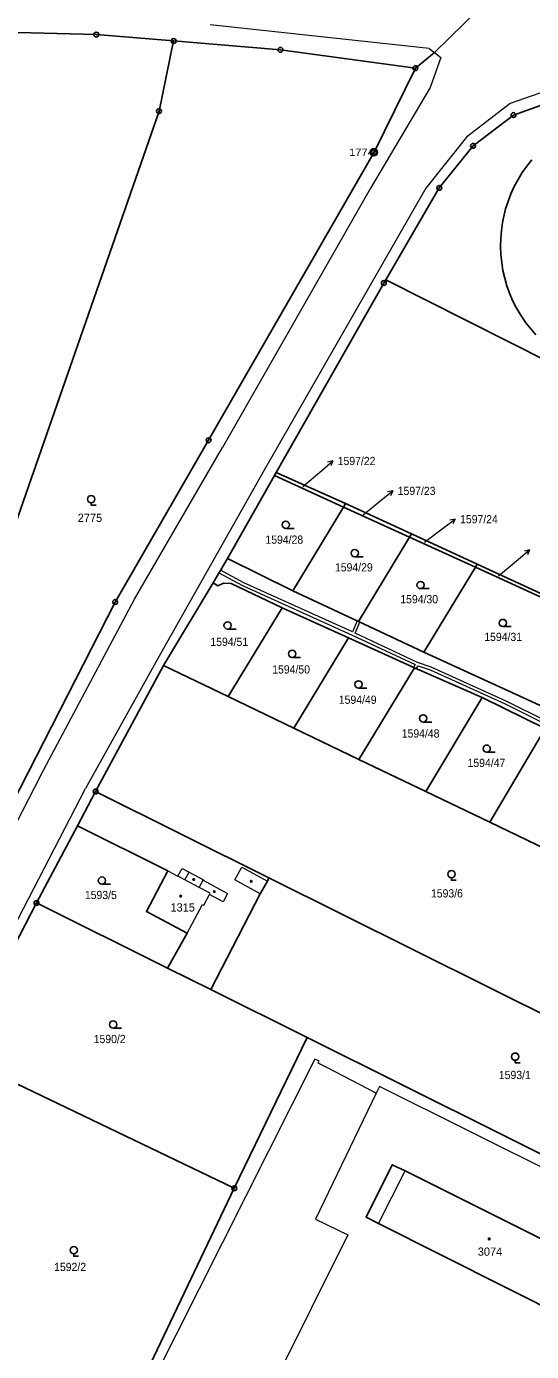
# Model space of a CAD drawing. Extents: x -679733 to -673243, y -1075091 to -1066557.
# Drawn here: x -677661.5 to -677557.1, y -1071678.8 to -1071405 of the extents above; entities that cross this region are included whole.
import ezdxf
from ezdxf.enums import TextEntityAlignment as Align

# ---------------------------------------------------------------- set-up
doc = ezdxf.new("R2010")
doc.units = 0
doc.header["$LTSCALE"] = 0.68
for name, color, linetype, lineweight in [('1', 7, 'Continuous', 25), ('13', 7, 'Continuous', 13), ('3', 7, 'Continuous', 25), ('4', 7, 'Continuous', 13), ('5', 7, 'Continuous', 25), ('7', 7, 'Continuous', 13), ('8', 7, 'Continuous', 25)]:
    doc.layers.add(name, color=color, linetype=linetype, lineweight=lineweight)
doc.layers.add('2', color=7, linetype='Continuous')

msp = doc.modelspace()

# ---------------------------------------------------------------- linework, layer by layer
at = {"layer": '1'}
for p, q in [((-677609.85, -1071497.19), (-677595.5, -1071503.6)), ((-677595.93, -1071504.31), (-677595.5, -1071503.6)), ((-677582.29, -1071510.53), (-677581.89, -1071509.87)), ((-677568.67, -1071516.74), (-677568.3, -1071516.13)), ((-677608.6, -1071525.12), (-677619.78, -1071543.45)), ((-677594.92, -1071531.34), (-677606.2, -1071549.97)), ((-677619.78, -1071543.45), (-677633.15, -1071537.04)), ((-677581.28, -1071537.54), (-677592.73, -1071556.43)), ((-677567.25, -1071543.65), (-677578.91, -1071563.07)), ((-677554.21, -1071550.04), (-677565.65, -1071569.43)), ((-677475.97, -1071648.33), (-677611.33, -1071580.93)), ((-677632.29, -1071599.54), (-677659.4, -1071586.1)), ((-677603.41, -1071613.91), (-677623.32, -1071603.99))]:
    msp.add_line(p, q, dxfattribs=at)
for points in [[(-677581.06, -1071413.63), (-677577.13, -1071410.43), (-677571, -1071404.43), (-677567.33, -1071400.82)], [(-677668.67, -1071406.15), (-677647.03, -1071406.71), (-677631.04, -1071408.03)], [(-677631.04, -1071408.03), (-677634.06, -1071422.51), (-677671.93, -1071531.12), (-677696.09, -1071583.01)], [(-677631.04, -1071408.03), (-677608.96, -1071409.86), (-677581.06, -1071413.63)], [(-677581.06, -1071413.63), (-677589.62, -1071430.98), (-677623.81, -1071490.51), (-677643.12, -1071523.94), (-677667.72, -1071571.95), (-677679.36, -1071592.98)], [(-677524.38, -1071416.45), (-677547.16, -1071418.48), (-677560.78, -1071423.33), (-677569.14, -1071429.68), (-677576.12, -1071438.38), (-677587.19, -1071457.4)], [(-677556.129, -1071468.742), (-677557.215, -1071467.524), (-677558.225, -1071466.241), (-677558.508, -1071465.851), (-677559.412, -1071464.492), (-677560.232, -1071463.081), (-677560.964, -1071461.622), (-677561.605, -1071460.121), (-677562.153, -1071458.583), (-677562.606, -1071457.015), (-677562.962, -1071455.422), (-677563.22, -1071453.81), (-677563.385, -1071452.16), (-677563.451, -1071450.503), (-677563.416, -1071448.846), (-677563.282, -1071447.193), (-677563.048, -1071445.552), (-677562.716, -1071443.927), (-677562.406, -1071442.734), (-677561.905, -1071441.154), (-677561.31, -1071439.606), (-677560.622, -1071438.097), (-677559.845, -1071436.633), (-677558.981, -1071435.218), (-677558.033, -1071433.857), (-677557.005, -1071432.556)], [(-677609.85, -1071497.19), (-677587.59, -1071458.03), (-677587.19, -1071457.4)], [(-677587.19, -1071457.4), (-677502.54, -1071500), (-677433.93, -1071533.74), (-677395.28, -1071552.08)], [(-677675.7, -1071617.62), (-677659.4, -1071586.1), (-677650.93, -1071570.15), (-677647.17, -1071563.08), (-677633.15, -1071537.04), (-677622.89, -1071519.94), (-677619.94, -1071514.94), (-677610.19, -1071497.8), (-677609.85, -1071497.19)], [(-677606.39, -1071521.59), (-677595.93, -1071504.31), (-677610.19, -1071497.8)], [(-677592.82, -1071527.94), (-677582.29, -1071510.53), (-677595.93, -1071504.31)], [(-677595.5, -1071503.6), (-677581.89, -1071509.87), (-677568.3, -1071516.13), (-677541.06, -1071528.61), (-677527.52, -1071534.91), (-677500.29, -1071547.58), (-677486.66, -1071553.87), (-677473.03, -1071560.16), (-677459.29, -1071566.4)], [(-677579.33, -1071534.29), (-677568.67, -1071516.74), (-677582.29, -1071510.53)], [(-677511.44, -1071565.66), (-677538.35, -1071553.02), (-677552.08, -1071546.78), (-677579.33, -1071534.29), (-677592.82, -1071527.94), (-677606.39, -1071521.59), (-677619.94, -1071514.94)], [(-677552.08, -1071546.78), (-677541.41, -1071529.19), (-677568.67, -1071516.74)], [(-677622.89, -1071519.94), (-677621.89, -1071520.58), (-677620.73, -1071520.03), (-677619.17, -1071520.07), (-677608.6, -1071525.12), (-677594.92, -1071531.34), (-677581.28, -1071537.54), (-677567.25, -1071543.65), (-677554.21, -1071550.04), (-677540.61, -1071556.25), (-677526.95, -1071562.58), (-677513.43, -1071569.04), (-677499.77, -1071575.57), (-677486.12, -1071581.93)], [(-677475.97, -1071648.33), (-677460.19, -1071618.11), (-677484.77, -1071607.17), (-677497.84, -1071601.35), (-677511.65, -1071595.21), (-677525.11, -1071588.88), (-677538.62, -1071582.4), (-677552.22, -1071575.88), (-677565.65, -1071569.43), (-677578.91, -1071563.07), (-677592.73, -1071556.43), (-677606.2, -1071549.97), (-677619.78, -1071543.45)], [(-677623.32, -1071603.99), (-677613.14, -1071584.19), (-677611.67, -1071581.57), (-677611.33, -1071580.93), (-677647.17, -1071563.08)], [(-677650.93, -1071570.15), (-677632.21, -1071579.49), (-677636.67, -1071587.87), (-677628.27, -1071592.32), (-677632.29, -1071599.54), (-677623.32, -1071603.99)], [(-677495.95, -1071734.2), (-677491.54, -1071711.22), (-677490.81, -1071708.2), (-677482.55, -1071674.1), (-677603.41, -1071613.91), (-677618.5, -1071645.05), (-677641.36, -1071692.91)], [(-677618.5, -1071645.05), (-677675.7, -1071617.62), (-677700.06, -1071664.74)]]:
    msp.add_lwpolyline(points, dxfattribs=at)
msp.add_lwpolyline([(-677536.2, -1071678.67), (-677588.68, -1071652.34), (-677591.25, -1071651), (-677585.84, -1071640.17), (-677583.21, -1071641.44), (-677530.69, -1071667.67)], close=True, dxfattribs=at)
at = {"layer": '13'}
msp.add_lwpolyline([(-677553.99, -1071548.56), (-677562.27, -1071544.42), (-677577.81, -1071537.38), (-677580.62, -1071536.42), (-677593.54, -1071530.36), (-677592.54, -1071528.07), (-677592.82, -1071527.94), (-677593.11, -1071527.8), (-677594.09, -1071530.11), (-677616.54, -1071519.99), (-677621.37, -1071517.36), (-677621.67, -1071517.88), (-677616.82, -1071520.51), (-677594.11, -1071530.76), (-677581.09, -1071536.86), (-677581.47, -1071537.45), (-677581.28, -1071537.54), (-677580.9, -1071537.7), (-677580.51, -1071537.09), (-677578.03, -1071537.94), (-677562.51, -1071544.96), (-677553.97, -1071549.25)], dxfattribs=at)
at = {"layer": '3'}
for p, q in [((-677607.863, -1071508.71), (-677606.113, -1071508.71)), ((-677593.603, -1071514.58), (-677591.853, -1071514.58)), ((-677579.993, -1071521.17), (-677578.243, -1071521.17)), ((-677619.883, -1071529.51), (-677618.133, -1071529.51)), ((-677562.983, -1071529.01), (-677561.233, -1071529.01)), ((-677606.543, -1071535.38), (-677604.793, -1071535.38)), ((-677592.823, -1071541.7), (-677591.073, -1071541.7)), ((-677579.443, -1071548.72), (-677577.693, -1071548.72)), ((-677566.323, -1071554.97), (-677564.573, -1071554.97)), ((-677645.863, -1071582.23), (-677644.113, -1071582.23)), ((-677643.543, -1071611.95), (-677641.793, -1071611.95))]:
    msp.add_line(p, q, dxfattribs=at)
for points in [[(-677648.09, -1071503.442), (-677648.09, -1071503.94), (-677647.089, -1071503.94)], [(-677573.61, -1071580.902), (-677573.61, -1071581.4), (-677572.609, -1071581.4)], [(-677560.43, -1071618.602), (-677560.43, -1071619.1), (-677559.429, -1071619.1)], [(-677651.69, -1071658.572), (-677651.69, -1071659.07), (-677650.689, -1071659.07)]]:
    msp.add_lwpolyline(points, dxfattribs=at)
for centre in [(-677648.0893, -1071502.6909), (-677607.8629, -1071507.9598), (-677593.6029, -1071513.8298), (-677579.9929, -1071520.4198), (-677619.8829, -1071528.7598), (-677562.9829, -1071528.2598), (-677606.5429, -1071534.6298), (-677592.8229, -1071540.9498), (-677579.4429, -1071547.9698), (-677566.3229, -1071554.2198), (-677573.6093, -1071580.1509), (-677645.8629, -1071581.4798), (-677643.5429, -1071611.1998), (-677560.4293, -1071617.8509), (-677651.6893, -1071657.8209)]:
    msp.add_circle(centre, 0.75, dxfattribs=at)
at = {"layer": '4'}
for p, q in [((-677578.23, -1071409.58), (-677623.48, -1071404.72)), ((-677578.23, -1071409.58), (-677577.13, -1071410.43)), ((-677575.78, -1071411.46), (-677578.02, -1071417.61)), ((-677577.13, -1071410.43), (-677575.78, -1071411.46)), ((-677578.02, -1071417.61), (-677590.43, -1071438.59)), ((-677548.01, -1071416.23), (-677561.48, -1071420.93)), ((-677561.48, -1071420.93), (-677570.5, -1071427.93)), ((-677570.5, -1071427.93), (-677578.92, -1071438.42)), ((-677590.43, -1071438.59), (-677620.95, -1071491.99)), ((-677578.92, -1071438.42), (-677612.34, -1071496.67)), ((-677639.12, -1071523.36), (-677620.95, -1071491.99)), ((-677612.34, -1071496.67), (-677634.05, -1071535.11)), ((-677658.49, -1071559.68), (-677639.12, -1071523.36)), ((-677634.05, -1071535.11), (-677649.28, -1071562.45)), ((-677658.49, -1071559.68), (-677713.36, -1071666.01)), ((-677704.66, -1071669.46), (-677649.28, -1071562.45)), ((-677630.15, -1071580.57), (-677629.3, -1071578.96)), ((-677629.3, -1071578.96), (-677627.86, -1071579.72)), ((-677618.42, -1071581.31), (-677616.97, -1071578.7)), ((-677616.97, -1071578.7), (-677611.67, -1071581.57)), ((-677632.21, -1071579.49), (-677630.15, -1071580.57)), ((-677628.71, -1071581.34), (-677630.15, -1071580.57)), ((-677628.71, -1071581.34), (-677627.86, -1071579.72)), ((-677625.74, -1071582.9), (-677628.71, -1071581.34)), ((-677627.86, -1071579.72), (-677624.89, -1071581.3)), ((-677625.74, -1071582.9), (-677624.95, -1071581.42)), ((-677624.89, -1071581.3), (-677624.95, -1071581.42)), ((-677624.95, -1071581.42), (-677619.93, -1071584.17)), ((-677613.14, -1071584.19), (-677618.42, -1071581.31)), ((-677623.5, -1071584.08), (-677625.74, -1071582.9)), ((-677624.82, -1071586.58), (-677623.64, -1071584.35)), ((-677623.64, -1071584.35), (-677623.5, -1071584.08)), ((-677620.81, -1071585.84), (-677623.64, -1071584.35)), ((-677619.93, -1071584.17), (-677620.81, -1071585.84)), ((-677628.27, -1071592.32), (-677625.08, -1071586.44)), ((-677625.08, -1071586.44), (-677624.82, -1071586.58)), ((-677601.83, -1071618.35), (-677639.79, -1071693.55)), ((-677600.95, -1071618.81), (-677601.83, -1071618.35)), ((-677601.13, -1071619.17), (-677600.95, -1071618.81)), ((-677599.35, -1071620.09), (-677601.13, -1071619.17)), ((-677589.14, -1071625.39), (-677599.35, -1071620.09)), ((-677589.14, -1071625.39), (-677601.68, -1071651.45)), ((-677588.49, -1071624.04), (-677589.14, -1071625.39)), ((-677526.82, -1071654.76), (-677588.49, -1071624.04)), ((-677588.68, -1071652.34), (-677583.21, -1071641.44)), ((-677601.68, -1071651.45), (-677595.02, -1071654.66)), ((-677595.02, -1071654.66), (-677618.98, -1071702.68))]:
    msp.add_line(p, q, dxfattribs=at)
at = {"layer": '5'}
for centre in [(-677626.9068, -1071581.2492), (-677614.9968, -1071581.6292), (-677629.5868, -1071584.6892), (-677622.6168, -1071583.7592), (-677565.8068, -1071655.4992)]:
    msp.add_circle(centre, 0.175, dxfattribs=at)
at = {"layer": '7'}
for p, q in [((-677598.145, -1071494.771), (-677599.229, -1071495.05)), ((-677585.738, -1071500.951), (-677586.831, -1071501.193)), ((-677572.833, -1071506.804), (-677573.934, -1071507.007)), ((-677557.441, -1071513.161), (-677558.53, -1071513.421))]:
    msp.add_line(p, q, dxfattribs=at)
for points in [[(-677604.3, -1071500.09), (-677600.41, -1071496.74), (-677598.145, -1071494.771), (-677598.572, -1071495.806)], [(-677591.89, -1071505.89), (-677588.07, -1071502.84), (-677585.738, -1071500.951), (-677586.201, -1071501.971)], [(-677579.18, -1071511.56), (-677575.23, -1071508.61), (-677572.833, -1071506.804), (-677573.332, -1071507.807)], [(-677563.91, -1071518.55), (-677559.74, -1071515.09), (-677557.441, -1071513.161), (-677557.886, -1071514.188)]]:
    msp.add_lwpolyline(points, dxfattribs=at)
at = {"layer": '8'}
for centre, radius in [((-677647.03, -1071406.7099), 0.5), ((-677647.03, -1071406.7099), 0.0303), ((-677631.04, -1071408.0299), 0.5), ((-677631.04, -1071408.0299), 0.0303), ((-677608.96, -1071409.8599), 0.5), ((-677608.96, -1071409.8599), 0.0303), ((-677581.06, -1071413.6299), 0.5), ((-677581.06, -1071413.6299), 0.0303), ((-677634.06, -1071422.5099), 0.5), ((-677634.06, -1071422.5099), 0.0303), ((-677560.78, -1071423.3299), 0.5), ((-677560.78, -1071423.3299), 0.0303), ((-677589.65, -1071431.0198), 0.75), ((-677589.62, -1071430.9799), 0.5), ((-677589.65, -1071431.0198), 0.03), ((-677589.62, -1071430.9799), 0.0303), ((-677569.14, -1071429.6799), 0.5), ((-677569.14, -1071429.6799), 0.0303), ((-677576.12, -1071438.3799), 0.5), ((-677576.12, -1071438.3799), 0.0303), ((-677587.59, -1071458.0299), 0.5), ((-677587.59, -1071458.0299), 0.0303), ((-677623.81, -1071490.5099), 0.5), ((-677623.81, -1071490.5099), 0.0303), ((-677643.12, -1071523.9399), 0.5), ((-677643.12, -1071523.9399), 0.0303), ((-677647.17, -1071563.0799), 0.5), ((-677647.17, -1071563.0799), 0.0303), ((-677659.4, -1071586.0999), 0.5), ((-677659.4, -1071586.0999), 0.0303), ((-677618.5, -1071645.0499), 0.5), ((-677618.5, -1071645.0499), 0.0303)]:
    msp.add_circle(centre, radius, dxfattribs=at)

# ---------------------------------------------------------------- texts
at = {"layer": '2', "width": 0.95}
for s, p in [('1597/22', (-677597.13, -1071495.64)), ('1597/23', (-677584.72, -1071501.82)), ('1597/24', (-677571.83, -1071507.67)), ('1594/28', (-677612.07, -1071511.89)), ('1594/29', (-677597.69, -1071517.61)), ('1594/30', (-677584.18, -1071524.2)), ('1594/51', (-677623.45, -1071532.999)), ('1594/31', (-677566.82, -1071531.979)), ('1594/50', (-677610.66, -1071538.7)), ('1594/49', (-677596.89, -1071544.96)), ('1594/48', (-677583.89, -1071551.93)), ('1594/47', (-677570.28, -1071558.009)), ('1593/5', (-677649.39, -1071585.3)), ('1593/6', (-677577.84, -1071584.96)), ('1590/2', (-677647.57, -1071615.05)), ('1593/1', (-677563.81, -1071622.479)), ('1592/2', (-677655.75, -1071662.14))]:
    msp.add_text(s, height=1.7, dxfattribs=at).set_placement(p)
at = {"layer": '2'}
msp.add_text('2775', height=1.7, dxfattribs=at).set_placement((-677648.34, -1071507.38), align=Align.CENTER)
for s, p in [('1315', (-677631.7, -1071587.87)), ('3074', (-677568.17, -1071658.979))]:
    msp.add_text(s, height=1.7, dxfattribs=at).set_placement(p)
at = {"layer": '8', "width": 1.15}
msp.add_text('1774', height=1.5, dxfattribs=at).set_placement((-677589.649, -1071431.77), align=Align.RIGHT)

doc.saveas('drawing.dxf')
